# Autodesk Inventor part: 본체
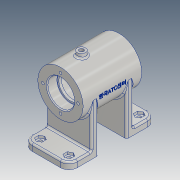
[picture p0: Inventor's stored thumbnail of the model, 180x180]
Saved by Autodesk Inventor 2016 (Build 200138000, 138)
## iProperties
Created: 2017-02
Part Number: 본체
Material: 알루미늄 6061
Document SubType Name: Modeling
Designer: CAMTIC
Density: 2.7 g/cm^3
Appearance: 알루미늄 - 평지
Mass: 355.336 g
Surface Area: 422.271 cm^2
Volume: 131.606 cm^3
Author: CAMTIC
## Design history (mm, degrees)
sketch "스케치1"
  geometry: L1 (-35, 27)-(35, 27); L2 (35, 27)-(35, 0); L3 (35, 0)-(-35, 0); L4 (-35, 0)-(-35, 27); L5 (-52, -52)-(52, -52); L6 (52, -52)-(52, -60); L7 (52, -60)-(-52, -60); L8 (-52, -60)-(-52, -52); L9 (-25, 0)-(-17, 0); L10 (-17, 0)-(-17, -52); L11 (-17, -52)-(-25, -52); L12 (-25, -52)-(-25, 0); L13 (17, 0)-(25, 0); L14 (25, 0)-(25, -52); L15 (25, -52)-(17, -52); L16 (17, -52)-(17, 0); L17 (0, -77.4)-(0, 44.4) reference; 3 further points
  constraints: 32 end point, 8 parallel, 4 horizontal, 4 perpendicular, 2 collinear, 2 midpoint, 2 point on line, 1 coincident, 1 vertical alignment
  dimensions: "d0" = 54 diameter of L1 L3; "d1" = 70 distance between parallel lines of L2 L4; "d2" = 8 distance of L5.end L6.end; "d3" = 104 distance of L6.end L7.end; "d4" = 60 distance from line of L3.end L7; "d5" = 8 distance of L9.start L9.end; "d6" = 8 distance of L13.start L13.end; "d7" = 17 distance from line of point (0, -52) L10; "d8" = 17 distance between parallel lines of L16 L17
revolve "회전1" stored, may be unused: angle "d9" = 90 deg
extrude "돌출1" join sketch "스케치1" stored distance "d10" = 54; taper "d12" = 0 deg; dims "d11" = 5, "d13" = 0
extrude "돌출2" join sketch "스케치1" stored distance "d14" = 54; taper "d15" = 0 deg
sketch "스케치2"
  geometry: L1 (-17, -34.654)-(17, -34.654); L2 (17, -34.654)-(17, -60); L3 (17, -60)-(-17, -60); L4 (-17, -60)-(-17, -34.654); L5 (-35, -27)-(35, -27) reference; L6 (-17, -52)-(-17, 0) reference; L7 (17, 0)-(17, -52) reference; L8 (-52, -60)-(52, -60) reference; 1 further point
  constraints: 8 end point, 3 collinear, 2 parallel, 1 horizontal, 1 perpendicular
  dimensions: "d16" = 25.34558 distance between parallel lines of L3 L1
extrude "돌출3" cut sketch "스케치2" stored distance "d17" = 54; taper "d18" = 0 deg
node "작업 평면1"
sketch "스케치3"
  geometry: L1 (52, -27)-(52, 27) reference; L2 (35, 27)-(35, -27) reference; C1 r 5 at (10, 0); 1 further point
  constraints: 1 centre point, 1 horizontal alignment
  dimensions: "d20" = 10 diameter of C1; "d24" = 25 distance from line of C1.centre L2
extrude "돌출4" join sketch "스케치3" stored distance "d22" = 54; taper "d23" = 0 deg
sketch "스케치4"
  geometry: L1 (-35, -27)-(-35, 27) reference; L2 (-35, 0)-(-23, 0); L3 (-23, 0)-(-23, 16); L4 (-23, 16)-(-35, 16); L5 (-35, 16)-(-35, 0); L6 (-23, 0)-(-20, 0); L7 (-20, 0)-(-20, 14); L8 (-20, 14)-(-23, 14); L9 (-23, 14)-(-23, 0); L10 (-20, 0)-(20, 0); L11 (20, 0)-(20, 22); L12 (20, 22)-(-20, 22); L13 (-20, 22)-(-20, 0); L14 (20, 0)-(23, 0); L15 (23, 0)-(23, 14); L16 (23, 14)-(20, 14); L17 (20, 14)-(20, 0); L18 (23, 0)-(35, 0); L19 (35, 0)-(35, 16); L20 (35, 16)-(23, 16); L21 (23, 16)-(23, 0); L22 (35, -27)-(35, 27) reference; 1 further point
  constraints: 40 end point, 10 parallel, 5 horizontal, 5 perpendicular, 1 collinear, 1 midpoint
  dimensions: "d25" = 12 distance of L3.end L4.end; "d26" = 3 distance of L7.end L8.end; "d27" = 3 distance of L15.end L16.end (= d26); "d28" = 12 distance of L19.end L20.end (= d25); "d29" = 32 diameter of L4 L2; "d30" = 28 diameter of L8 L6; "d31" = 44 diameter of L12 L10; "d32" = 28 diameter of L16 L14; "d33" = 32 diameter of L20 L18
revolve "회전2" sketch "스케치4" stored, may be unused: angle "d34" = 90 deg
fillet "모깎기1" dims "d35" = 3
fillet "모깎기2" dims "d36" = 0.3
chamfer "모따기1" distance "d37" = 1; stored, may be unused: second distance "d38" = 2, angle "d39" = 45 deg
sketch "스케치5"
  geometry: C1 r 5 at (0, 0) reference; 1 further point
hole "구멍1" sketch "스케치5" at (0, 0) diameter "d40" = 5.188; stored, may be unused: countersink angle "d44" = 90 deg, drill point angle "d46" = 0 deg; dims "d41" = 12, "d42" = 4, "d43" = 2, "d45" = 16
fillet "모깎기3" dims "d47" = 2
sketch "스케치6"
  geometry: L1 (0, 0)-(-25.16, -16.339); L2 (0, 0)-(-44.384, 0); C1 r 14 at (0, 0) reference; 1 further point
  constraints: 4 end point, 1 horizontal
  dimensions: "d48" = 30 distance of L1.start L1.end; "d49" = 33 deg angle of L1 L2
node "작업 평면2"
sketch "스케치7"
  geometry: C1 r 6 at (0, 0); 1 further point
  constraints: 1 centre point, 1 coincident
  dimensions: "d50" = 12 diameter of C1
extrude "돌출5" join sketch "스케치7" stored distance "d51" = 54; taper "d52" = 0 deg
sketch "스케치8"
  geometry: C1 r 6 at (0, 0) reference; 2 further points
  constraints: 1 coincident
hole "구멍2" sketch "스케치8" at (0, 0), (0, 0) diameter "d53" = 5.188; stored, may be unused: countersink angle "d57" = 90 deg, drill point angle "d59" = 0 deg; dims "d54" = 12, "d55" = 4, "d56" = 2, "d58" = 16
fillet "모깎기4" dims "d60" = 2
sketch "스케치9" dims "d61" = 42
  geometry: L1 (0, 0)-(0, 21); C1 r 27 at (0, 0) reference; C2 r 14 at (0, 0) reference; 3 further points
  constraints: 2 coincident, 2 end point, 1 vertical, 1 vertical alignment, 2 other
hole "구멍3" sketch "스케치9" at (0, 21) diameter "d62" = 3.242; stored, may be unused: countersink angle "d66" = 90 deg, drill point angle "d68" = 118 deg; dims "d63" = 8, "d64" = 4, "d65" = 2, "d67" = 10
node "작업 평면4"
sketch "스케치10"
  geometry: L1 (-35, 27)-(35, 27) reference; L2 (-35, -27)-(-35, 27) reference; 2 further points
  constraints: 1 coincident, 1 other
  dimensions: "d73" = 27 distance from line of point (0, 0) L1; "d74" = 35 distance from line of point (0, 0) L2 (derived)
feature "엠보싱1" sketch "스케치10" dims "d12" = 0, "d75" = 0.5, "d76" = 0
fillet "모깎기5" dims "d77" = 10
sketch "스케치11" dims "d98" = 9, "d99" = 9, "d100" = 9, "d101" = 9
  geometry: L1 (17, 54)-(-8, 54) reference; L2 (27, 10)-(27, 44) reference; L3 (-25, 64.9)-(-25, -11.401) reference; L4 (19.598, 48.5)-(22.196, 44); L5 (22.196, 44)-(19.598, 39.5); L6 (19.598, 39.5)-(14.402, 39.5); L7 (14.402, 39.5)-(11.804, 44); L8 (11.804, 44)-(14.402, 48.5); L9 (14.402, 48.5)-(19.598, 48.5); L10 (11.804, 44)-(22.196, 44); L11 (14.402, 39.5)-(19.598, 48.5); L12 (19.598, 39.5)-(14.402, 48.5); L13 (19.598, 14.5)-(22.196, 10); L14 (22.196, 10)-(19.598, 5.5); L15 (19.598, 5.5)-(14.402, 5.5); L16 (14.402, 5.5)-(11.804, 10); L17 (11.804, 10)-(14.402, 14.5); L18 (14.402, 14.5)-(19.598, 14.5); L19 (11.804, 10)-(22.196, 10); L20 (14.402, 5.5)-(19.598, 14.5); L21 (19.598, 5.5)-(14.402, 14.5); L22 (-64.402, 14.5)-(-61.804, 10); L23 (-61.804, 10)-(-64.402, 5.5); L24 (-64.402, 5.5)-(-69.598, 5.5); L25 (-69.598, 5.5)-(-72.196, 10); L26 (-72.196, 10)-(-69.598, 14.5); L27 (-69.598, 14.5)-(-64.402, 14.5); L28 (-72.196, 10)-(-61.804, 10); L29 (-69.598, 5.5)-(-64.402, 14.5); L30 (-64.402, 5.5)-(-69.598, 14.5); L31 (-64.402, 48.5)-(-61.804, 44); L32 (-61.804, 44)-(-64.402, 39.5); L33 (-64.402, 39.5)-(-69.598, 39.5); L34 (-69.598, 39.5)-(-72.196, 44); L35 (-72.196, 44)-(-69.598, 48.5); L36 (-69.598, 48.5)-(-64.402, 48.5); L37 (-72.196, 44)-(-61.804, 44); L38 (-69.598, 39.5)-(-64.402, 48.5); L39 (-64.402, 39.5)-(-69.598, 48.5); 27 further points
  constraints: 72 end point, 11 midpoint, 8 coincident, 4 horizontal, 2 symmetric about line, 2 vertical alignment, 63 other
  dimensions: "d78" = 34 distance of point (17, 10) point (17, 44); "d79" = 10 distance from line of L1 point (17, 44); "d80" = 10 distance from line of point (17, 44) L2
extrude "돌출6" cut sketch "스케치11" distance "d85" = 3; taper "d86" = 0 deg
sketch "스케치12"
  geometry: L1 (-64.402, 14.5)-(-69.598, 14.5) reference; L2 (-69.598, 14.5)-(-72.196, 10) reference; L3 (-72.196, 10)-(-69.598, 5.5) reference; L4 (-69.598, 5.5)-(-64.402, 5.5) reference; L5 (-64.402, 5.5)-(-61.804, 10) reference; L6 (-61.804, 10)-(-64.402, 14.5) reference; L7 (19.598, 48.5)-(14.402, 48.5) reference; L8 (14.402, 48.5)-(11.804, 44) reference; L9 (11.804, 44)-(14.402, 39.5) reference; L10 (14.402, 39.5)-(19.598, 39.5) reference; L11 (19.598, 39.5)-(22.196, 44) reference; L12 (22.196, 44)-(19.598, 48.5) reference; L13 (19.598, 14.5)-(14.402, 14.5) reference; L14 (14.402, 14.5)-(11.804, 10) reference; L15 (11.804, 10)-(14.402, 5.5) reference; L16 (14.402, 5.5)-(19.598, 5.5) reference; L17 (19.598, 5.5)-(22.196, 10) reference; L18 (22.196, 10)-(19.598, 14.5) reference; L19 (-64.402, 48.5)-(-69.598, 48.5) reference; L20 (-69.598, 48.5)-(-72.196, 44) reference; L21 (-72.196, 44)-(-69.598, 39.5) reference; L22 (-69.598, 39.5)-(-64.402, 39.5) reference; L23 (-64.402, 39.5)-(-61.804, 44) reference; L24 (-61.804, 44)-(-64.402, 48.5) reference; L25 (-67, 54)-(-42, 54) reference; L26 (-42, 54)-(-42, 0) reference; L27 (-42, 0)-(-67, 0) reference; L28 (-77, 10)-(-77, 44) reference; L29 (27, 44)-(27, 10) reference; L30 (17, 0)-(-8, 0) reference; L31 (-8, 0)-(-8, 54) reference; L32 (-8, 54)-(17, 54) reference; A1 r 10 centre (-67, 44) between (-67, 54) and (-77, 44) reference; A2 r 10 centre (-67, 10) between (-77, 10) and (-67, 0) reference; A3 r 10 centre (17, 44) between (27, 44) and (17, 54) reference; A4 r 10 centre (17, 10) between (17, 0) and (27, 10) reference; 1 further point
hole "구멍4" sketch "스케치12" at (17, 44), (17, 10), (-67, 10), (-67, 44) diameter "d87" = 5; stored, may be unused: countersink angle "d91" = 90 deg, drill point angle "d93" = 118 deg; dims "d88" = 8, "d89" = 4, "d90" = 2, "d92" = 10
fillet "모깎기6" dims "d94" = 2
fillet "모깎기7" dims "d95" = 2
fillet "모깎기8" dims "d96" = 2
fillet "모깎기9" dims "d97" = 2
node "솔리드1"
pattern_circular "원형 패턴1" dims angle "d70" = 360 deg
mirror "대칭1"
node "작업 평면3"
node "절단 모서리 투영1"
other parameters: "d19" = 32
